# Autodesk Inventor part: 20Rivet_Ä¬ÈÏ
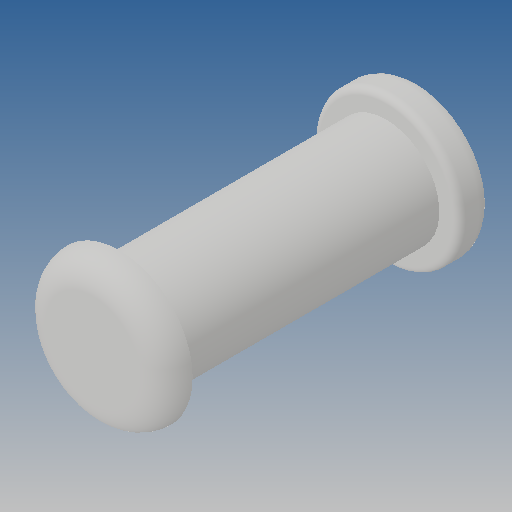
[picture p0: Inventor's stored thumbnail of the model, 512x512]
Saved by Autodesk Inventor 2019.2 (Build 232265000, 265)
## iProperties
Created: 2010-06
Part Number: 20Rivet_Ä¬ÈÏ
Material: Ogólny
Document SubType Name: Modeling
Designer: CADENGINEERING4
Density: 1 g/cm^3
Appearance: Domyślna
Author: CADENGINEERING4
Revision Number: ÈÎºÎ
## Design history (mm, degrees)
feature "NONE"
node "Bryła1"
